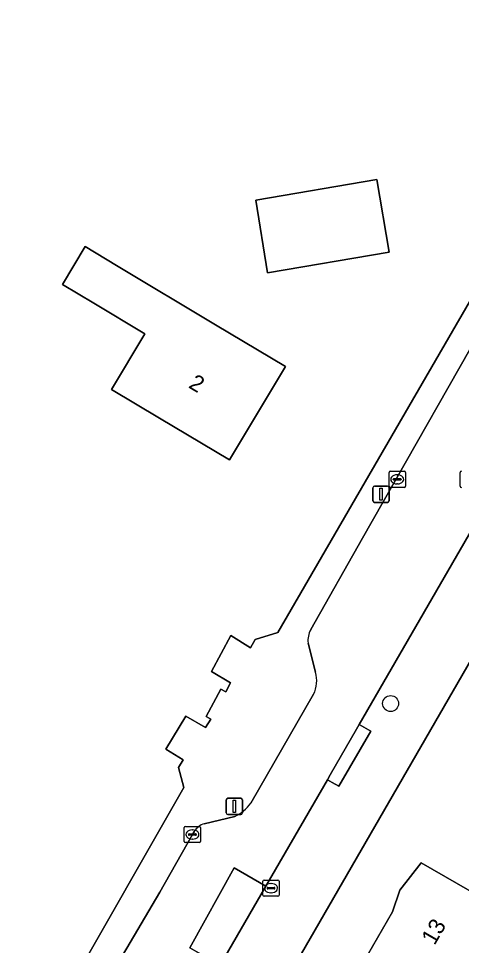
# Model space of a CAD drawing. Extents: x 161772 to 163126, y 383092 to 383917.
# Drawn here: x 162368.9 to 162396.1, y 383548.4 to 383605.3 of the extents above; entities that cross this region are included whole.
import ezdxf

# ---------------------------------------------------------------- set-up
doc = ezdxf.new("R2010")
doc.units = 0
for name, color, linetype in [('IMGEO_Boom', 7, 'Continuous'), ('IMGEO_Erf', 7, 'Continuous'), ('IMGEO_Kolk', 7, 'Continuous'), ('IMGEO_Lichtmast', 7, 'Continuous'), ('IMGEO_Pand', 7, 'Continuous'), ('IMGEO_Pand_nummerreeks', 7, 'Continuous'), ('IMGEO_Parkeervlak_open', 7, 'Continuous'), ('IMGEO_Rijbaan_lokaal_open', 7, 'Continuous'), ('IMGEO_Rioolput', 7, 'Continuous'), ('IMGEO_Voetpad_open', 7, 'Continuous')]:
    doc.layers.add(name, color=color, linetype=linetype)

msp = doc.modelspace()

# ---------------------------------------------------------------- linework, layer by layer
at = {"layer": 'IMGEO_Boom'}
msp.add_circle((162391.714, 383563.253), 0.489, dxfattribs=at)
at = {"layer": 'IMGEO_Erf'}
for points in [[(162462.704, 383536.779), (162483.744, 383554.98), (162500, 383574.599), (162526.947, 383607.122), (162543.804, 383623.317), (162548.918, 383628.126), (162539.791, 383641.093), (162527.133, 383641.683), (162527.105, 383641.456), (162500, 383642.583), (162442.25, 383644.984), (162375.184, 383528.714), (162418.191, 383500), (162425.357, 383495.215)], [(162300.454, 383528.48), (162364.66, 383532.938), (162379.033, 383558.1), (162378.697, 383559.319), (162378.986, 383559.791), (162377.92, 383560.443), (162379.141, 383562.484), (162380.354, 383561.791), (162380.691, 383562.293), (162380.39, 383562.462), (162381.3, 383564.126), (162381.601, 383563.978), (162381.897, 383564.519), (162380.724, 383565.212), (162381.917, 383567.437), (162383.121, 383566.67), (162383.404, 383567.188), (162384.796, 383567.606), (162426.383, 383639.462)]]:
    msp.add_lwpolyline(points, dxfattribs=at)
for points in [[(162384.167, 383589.709), (162383.448, 383594.164), (162390.869, 383595.436), (162391.624, 383590.963)], [(162373.503, 383587.843), (162371.579, 383588.995), (162372.965, 383591.31), (162374.889, 383590.158), (162380.969, 383586.519), (162385.259, 383583.951), (162381.825, 383578.212), (162377.535, 383580.78), (162374.59, 383582.542), (162376.639, 383585.966)], [(162403.237, 383547.907), (162401.898, 383545.585), (162406.58, 383542.884), (162404.688, 383539.603), (162405.169, 383539.325), (162403.429, 383536.318), (162396.892, 383540.091), (162395.303, 383537.337), (162392.84, 383538.758), (162391.616, 383536.638), (162387.504, 383539.01), (162388.727, 383541.13), (162386.934, 383542.164), (162387.871, 383544.22), (162389.006, 383545.559), (162390.298, 383547.799), (162391.838, 383550.468), (162392.281, 383551.799), (162393.595, 383553.469), (162397.927, 383550.97)]]:
    msp.add_lwpolyline(points, close=True, dxfattribs=at)
at = {"layer": 'IMGEO_Kolk'}
for p, q in [((162391.619, 383576.594), (162391.619, 383577.446)), ((162391.694, 383577.52), (162392.546, 383577.52)), ((162391.921, 383577.063), (162392.319, 383577.063)), ((162392.107, 383577.3), (162392.132, 383577.3)), ((162392.62, 383577.446), (162392.62, 383576.594)), ((162392.546, 383576.52), (162391.694, 383576.52)), ((162391.878, 383577.014), (162391.878, 383577.026)), ((162392.316, 383576.977), (162391.918, 383576.977)), ((162392.13, 383576.74), (162392.105, 383576.74)), ((162392.362, 383577.026), (162392.362, 383577.014)), ((162379.053, 383554.784), (162379.053, 383555.636)), ((162379.128, 383555.71), (162379.98, 383555.71)), ((162379.541, 383555.49), (162379.566, 383555.49)), ((162380.054, 383555.636), (162380.054, 383554.784)), ((162379.312, 383555.204), (162379.312, 383555.216)), ((162379.75, 383555.167), (162379.352, 383555.167)), ((162379.355, 383555.253), (162379.753, 383555.253)), ((162379.564, 383554.93), (162379.539, 383554.93)), ((162379.796, 383555.216), (162379.796, 383555.204)), ((162379.98, 383554.71), (162379.128, 383554.71)), ((162383.875, 383551.49), (162383.875, 383552.342)), ((162383.95, 383552.416), (162384.802, 383552.416)), ((162384.363, 383552.196), (162384.388, 383552.196)), ((162384.876, 383552.342), (162384.876, 383551.49)), ((162384.134, 383551.91), (162384.134, 383551.922)), ((162384.572, 383551.873), (162384.174, 383551.873)), ((162384.177, 383551.959), (162384.575, 383551.959)), ((162384.386, 383551.636), (162384.361, 383551.636)), ((162384.618, 383551.922), (162384.618, 383551.91)), ((162384.802, 383551.416), (162383.95, 383551.416))]:
    msp.add_line(p, q, dxfattribs=at)
for points in [[(162391.619, 383576.594), (162391.619, 383577.446)], [(162391.694, 383577.52), (162392.546, 383577.52)], [(162392.62, 383577.446), (162392.62, 383576.594)], [(162392.546, 383576.52), (162391.694, 383576.52)], [(162379.053, 383554.784), (162379.053, 383555.636)], [(162379.128, 383555.71), (162379.98, 383555.71)], [(162380.054, 383555.636), (162380.054, 383554.784)], [(162379.98, 383554.71), (162379.128, 383554.71)], [(162383.875, 383551.49), (162383.875, 383552.342)], [(162383.95, 383552.416), (162384.802, 383552.416)], [(162384.876, 383552.342), (162384.876, 383551.49)], [(162384.802, 383551.416), (162383.95, 383551.416)]]:
    msp.add_lwpolyline(points, dxfattribs=at)
for centre, radius, start, end in [((162391.696, 383577.444), 0.0765, 91.552, 178.448), ((162391.696, 383577.444), 0.0765, 91.552, 178.448), ((162391.918, 383577.023), 0.0403, 85.8775, 175.7526), ((162392.323, 383577.025), 0.0386, 1.7309, 96.639), ((162392.544, 383577.444), 0.0765, 1.552, 88.448), ((162392.544, 383577.444), 0.0765, 1.552, 88.448), ((162391.696, 383576.596), 0.0765, 181.552, 268.448), ((162391.696, 383576.596), 0.0765, 181.552, 268.448), ((162391.915, 383577.013), 0.0366, 178.938, 274.7102), ((162392.319, 383577.02), 0.043, 264.8664, 352.4533), ((162392.544, 383576.596), 0.0765, 271.552, 358.448), ((162392.544, 383576.596), 0.0765, 271.552, 358.448), ((162379.13, 383555.634), 0.0765, 91.552, 178.448), ((162379.13, 383555.634), 0.0765, 91.552, 178.448), ((162379.978, 383555.634), 0.0765, 1.552, 88.448), ((162379.978, 383555.634), 0.0765, 1.552, 88.448), ((162379.352, 383555.213), 0.0403, 85.8775, 175.7526), ((162379.349, 383555.203), 0.0366, 178.938, 274.7102), ((162379.753, 383555.21), 0.043, 264.8664, 352.4533), ((162379.757, 383555.215), 0.0386, 1.7309, 96.639), ((162379.13, 383554.786), 0.0765, 181.552, 268.448), ((162379.13, 383554.786), 0.0765, 181.552, 268.448), ((162379.978, 383554.786), 0.0765, 271.552, 358.448), ((162379.978, 383554.786), 0.0765, 271.552, 358.448), ((162383.952, 383552.34), 0.0765, 91.552, 178.448), ((162383.952, 383552.34), 0.0765, 91.552, 178.448), ((162384.8, 383552.34), 0.0765, 1.552, 88.448), ((162384.8, 383552.34), 0.0765, 1.552, 88.448), ((162383.952, 383551.492), 0.0765, 181.552, 268.448), ((162383.952, 383551.492), 0.0765, 181.552, 268.448), ((162384.174, 383551.919), 0.0403, 85.8775, 175.7526), ((162384.171, 383551.909), 0.0366, 178.938, 274.7102), ((162384.575, 383551.916), 0.043, 264.8664, 352.4533), ((162384.579, 383551.921), 0.0386, 1.7309, 96.639), ((162384.8, 383551.492), 0.0765, 271.552, 358.448), ((162384.8, 383551.492), 0.0765, 271.552, 358.448)]:
    msp.add_arc(centre, radius, start, end, dxfattribs=at)
for centre, major_axis, ratio, start_param, end_param in [((162392.106, 383577.02), (-0.387, 0.002), 0.722429, 4.712389, 7.853982), ((162392.131, 383577.02), (-0.39, 0.002), 0.717154, 1.570796, 4.712389), ((162379.54, 383555.21), (-0.387, 0.002), 0.722429, 4.712389, 7.853982), ((162379.565, 383555.21), (-0.39, 0.002), 0.717154, 1.570796, 4.712389), ((162384.362, 383551.916), (-0.387, 0.002), 0.722429, 4.712389, 7.853982), ((162384.387, 383551.916), (-0.39, 0.002), 0.717154, 1.570796, 4.712389)]:
    msp.add_ellipse(centre, major_axis=major_axis, ratio=ratio, start_param=start_param, end_param=end_param, dxfattribs=at)
at = {"layer": 'IMGEO_Lichtmast'}
for p, q in [((162390.632, 383575.707), (162390.632, 383576.507)), ((162390.632, 383576.507), (162390.632, 383575.707)), ((162390.732, 383576.607), (162391.522, 383576.607)), ((162391.522, 383576.607), (162390.732, 383576.607)), ((162391.622, 383576.507), (162391.622, 383575.707)), ((162391.622, 383575.707), (162391.622, 383576.507)), ((162391.522, 383575.607), (162390.732, 383575.607)), ((162390.732, 383575.607), (162391.522, 383575.607)), ((162381.631, 383556.538), (162381.631, 383557.338)), ((162381.631, 383557.338), (162381.631, 383556.538)), ((162381.731, 383557.438), (162382.521, 383557.438)), ((162382.521, 383557.438), (162381.731, 383557.438)), ((162382.621, 383557.338), (162382.621, 383556.538)), ((162382.621, 383556.538), (162382.621, 383557.338)), ((162382.521, 383556.438), (162381.731, 383556.438)), ((162381.731, 383556.438), (162382.521, 383556.438))]:
    msp.add_line(p, q, dxfattribs=at)
for points in [[(162391.052, 383576.482), (162391.202, 383576.482), (162391.202, 383575.732), (162391.052, 383575.732), (162391.052, 383576.482)], [(162382.051, 383557.313), (162382.201, 383557.313), (162382.201, 383556.563), (162382.051, 383556.563), (162382.051, 383557.313)]]:
    msp.add_lwpolyline(points, dxfattribs=at)
for centre, start, end in [((162390.732, 383576.507), 90, 180), ((162390.732, 383576.507), 90, 180), ((162391.522, 383576.507), 0, 90), ((162391.522, 383576.507), 360, 90), ((162390.732, 383575.707), 180, 270), ((162390.732, 383575.707), 180, 270), ((162391.522, 383575.707), 270, 0), ((162391.522, 383575.707), 270, 0), ((162381.731, 383557.338), 90, 180), ((162381.731, 383557.338), 90, 180), ((162382.521, 383557.338), 0, 90), ((162382.521, 383557.338), 360, 90), ((162381.731, 383556.538), 180, 270), ((162381.731, 383556.538), 180, 270), ((162382.521, 383556.538), 270, 0), ((162382.521, 383556.538), 270, 0)]:
    msp.add_arc(centre, 0.1, start, end, dxfattribs=at)
at = {"layer": 'IMGEO_Pand'}
for points in [[(162384.167, 383589.709), (162391.624, 383590.963), (162390.869, 383595.436), (162383.448, 383594.164)], [(162380.969, 383586.519), (162374.889, 383590.158), (162372.965, 383591.31), (162371.579, 383588.995), (162373.503, 383587.843), (162376.639, 383585.966), (162374.59, 383582.542), (162377.535, 383580.78), (162381.825, 383578.212), (162385.259, 383583.951)], [(162390.298, 383547.799), (162404.567, 383539.393), (162404.688, 383539.603), (162406.58, 383542.884), (162401.898, 383545.585), (162403.237, 383547.907), (162397.927, 383550.97), (162393.595, 383553.469), (162392.281, 383551.799), (162391.838, 383550.468)]]:
    msp.add_lwpolyline(points, close=True, dxfattribs=at)
at = {"layer": 'IMGEO_Parkeervlak_open'}
msp.add_lwpolyline([(162384.067, 383552.041), (162382.112, 383553.168), (162379.395, 383548.254), (162381.266, 383547.185)], close=True, dxfattribs=at)
at = {"layer": 'IMGEO_Rijbaan_lokaal_open'}
for points in [[(162396.733, 383574.003), (162399.866, 383579.435), (162405.394, 383589.019), (162408.417, 383594.261), (162411.358, 383599.359), (162406.588, 383602.114), (162405.755, 383600.666), (162402.632, 383595.376), (162400.903, 383592.448), (162398.603, 383588.553), (162389.993, 383573.403), (162386.81, 383567.805)], [(162379.672, 383555.407), (162379.555, 383555.209), (162377.558, 383551.679), (162371.417, 383541.25), (162369.018, 383537.045), (162372.207, 383535.252), (162372.39, 383535.583), (162375.755, 383541.669), (162377.549, 383540.643), (162381.266, 383547.185), (162379.395, 383548.254), (162382.112, 383553.168), (162384.067, 383552.041), (162387.836, 383558.577), (162388.004, 383558.867), (162389.62, 383561.671), (162389.788, 383561.962), (162396.733, 383574.003)], [(162386.647, 383566.966), (162387.096, 383565.173)], [(162386.987, 383563.819), (162383.14, 383557.135)], [(162382.16, 383556.319), (162380.28, 383555.874)]]:
    msp.add_lwpolyline(points, dxfattribs=at)
for centre, radius, start, end in [((162388.206, 383567.098), 1.564, 153.153, 184.8582), ((162385.354, 383564.632), 1.824, 333.5339, 17.261), ((162380.933, 383558.789), 2.758, 296.4137, 323.1514), ((162380.649, 383554.764), 1.17, 108.396, 146.6592)]:
    msp.add_arc(centre, radius, start, end, dxfattribs=at)
at = {"layer": 'IMGEO_Rioolput'}
msp.add_line((162395.985, 383576.593), (162395.985, 383577.445), dxfattribs=at)
msp.add_lwpolyline([(162395.985, 383576.593), (162395.985, 383577.445)], dxfattribs=at)
for centre, start, end in [((162396.062, 383577.443), 91.552, 178.448), ((162396.062, 383577.443), 91.552, 178.448), ((162396.062, 383576.595), 181.552, 268.448), ((162396.062, 383576.595), 181.552, 268.448)]:
    msp.add_arc(centre, 0.0765, start, end, dxfattribs=at)
at = {"layer": 'IMGEO_Voetpad_open'}
for points in [[(162375.184, 383528.714), (162442.25, 383644.984)], [(162427.251, 383641.753), (162426.383, 383639.462), (162384.796, 383567.606), (162383.404, 383567.188), (162383.121, 383566.67), (162381.917, 383567.437), (162380.724, 383565.212), (162381.897, 383564.519), (162381.601, 383563.978), (162381.3, 383564.126), (162380.39, 383562.462), (162380.691, 383562.293), (162380.354, 383561.791), (162379.141, 383562.484), (162377.92, 383560.443), (162378.986, 383559.791), (162378.697, 383559.319), (162379.033, 383558.1), (162364.66, 383532.938)], [(162386.81, 383567.805), (162389.993, 383573.403), (162398.603, 383588.553), (162398.398, 383588.673), (162400.693, 383592.572), (162400.903, 383592.448), (162402.632, 383595.376), (162402.417, 383595.503), (162405.532, 383600.797), (162405.755, 383600.666), (162406.588, 383602.114), (162407.845, 383604.299), (162427.335, 383638.205), (162428.716, 383640.58), (162429.004, 383641.083)], [(162416.63, 383608.502), (162413.855, 383603.69), (162412.617, 383601.543), (162411.358, 383599.359), (162408.417, 383594.261), (162408.708, 383594.093), (162409.199, 383593.81), (162406.182, 383588.565), (162405.685, 383588.851), (162405.394, 383589.019), (162399.866, 383579.435), (162400.157, 383579.267), (162400.596, 383579.01), (162397.432, 383573.596), (162397.024, 383573.835), (162396.733, 383574.003), (162389.788, 383561.962), (162390.079, 383561.794), (162390.492, 383561.556), (162388.543, 383558.17), (162388.127, 383558.409), (162387.836, 383558.577), (162384.067, 383552.041), (162381.266, 383547.185)], [(162387.096, 383565.173), (162386.647, 383566.966)], [(162383.14, 383557.135), (162386.987, 383563.819)], [(162380.28, 383555.874), (162382.16, 383556.319)], [(162371.417, 383541.25), (162377.558, 383551.679), (162379.555, 383555.209), (162379.672, 383555.407)]]:
    msp.add_lwpolyline(points, dxfattribs=at)
msp.add_lwpolyline([(162390.492, 383561.556), (162390.079, 383561.794), (162389.788, 383561.962), (162389.62, 383561.671), (162388.004, 383558.867), (162387.836, 383558.577), (162388.127, 383558.409), (162388.543, 383558.17)], close=True, dxfattribs=at)
for centre, radius, start, end in [((162388.206, 383567.098), 1.564, 153.153, 184.8582), ((162385.354, 383564.632), 1.824, 333.5339, 17.261), ((162380.933, 383558.789), 2.758, 296.4137, 323.1514), ((162380.649, 383554.764), 1.17, 108.396, 146.6592)]:
    msp.add_arc(centre, radius, start, end, dxfattribs=at)

# ---------------------------------------------------------------- texts
at = {"layer": 'IMGEO_Pand_nummerreeks'}
for s, rotation, p in [('2', 329.1004, (162379.263, 383582.682)), ('13', 60.0194, (162394.411, 383548.364))]:
    msp.add_text(s, height=1, rotation=rotation, dxfattribs=at).set_placement(p)

doc.saveas('drawing.dxf')
